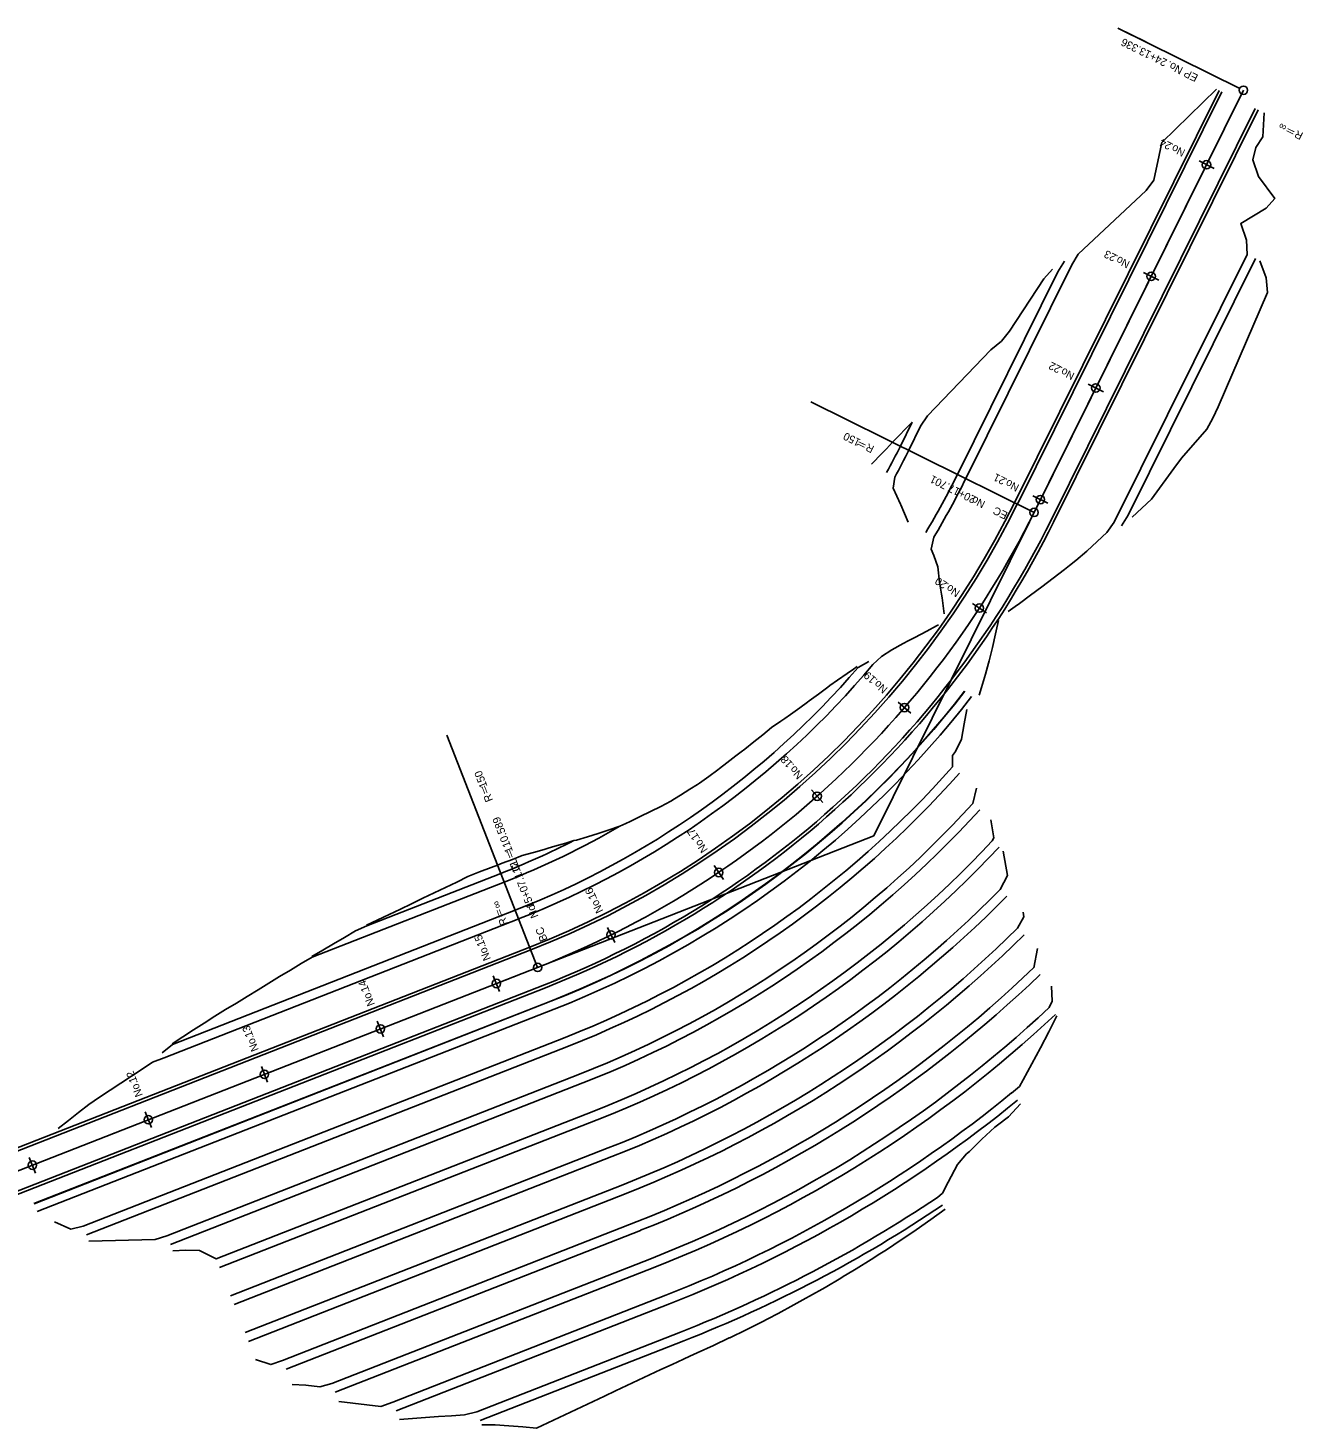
# Model space of a CAD drawing. Extents: x 46571 to 46965, y 10701 to 11034.
# Drawn here: x 46760.7 to 46965.4, y 10809 to 11033.7 of the extents above; entities that cross this region are included whole.
import ezdxf

# ---------------------------------------------------------------- set-up
doc = ezdxf.new("R2010")
doc.units = 0
for name, color, linetype in [('Default', 7, 'Continuous'), ('作業レイヤ1', 7, 'Continuous'), ('地形_土崖 コンクリート、堅固な石積等斜面（地理院地図Vector）', 7, 'Continuous'), ('建物_堅ろう建物_堅ろう建物（外周線）（地理院地図Vector）', 7, 'Continuous'), ('建物_普通建物_普通建物（外周線）（地理院地図Vector）', 7, 'Continuous'), ('河川_通常部（地理院地図Vector）', 7, 'Continuous'), ('現況_地形', 7, 'Continuous'), ('現況_地形_フロー矢印', 7, 'Continuous'), ('現況_地形_単点標高', 7, 'Continuous'), ('等高線等深線_等高線_主曲線通常部（地理院地図Vector）', 7, 'Continuous'), ('道路_通常部_通常部（地理院地図Vector）', 7, 'Continuous')]:
    doc.layers.add(name, color=color, linetype=linetype)

msp = doc.modelspace()

# ---------------------------------------------------------------- linework, layer by layer
at = {"layer": 'Default'}
for p, q in [((46955.22, 11024.01), (46935.66, 11033.7)), ((46935.66, 11033.7), (46940.14, 11031.48)), ((46896.47, 10904.04), (46955.82, 11023.71)), ((46922.21, 10955.95), (46955.82, 11023.71)), ((46955.82, 11023.71), (46955.82, 11023.71)), ((46949.89, 11011.76), (46949.89, 11011.76)), ((46941.01, 10993.84), (46941.01, 10993.84)), ((46932.12, 10975.92), (46932.12, 10975.92)), ((46922.21, 10955.95), (46886.38, 10973.72)), ((46923.23, 10958.01), (46923.23, 10958.01)), ((46922.21, 10955.95), (46922.21, 10955.95)), ((46913.43, 10940.59), (46913.43, 10940.59)), ((46901.41, 10924.62), (46901.41, 10924.62)), ((46842.51, 10882.92), (46827.93, 10920.17)), ((46887.38, 10910.39), (46887.38, 10910.39)), ((46679.76, 10819.21), (46896.47, 10904.04)), ((46871.58, 10898.15), (46871.58, 10898.15)), ((46854.29, 10888.13), (46854.29, 10888.13)), ((46720.93, 10835.33), (46842.51, 10882.92)), ((46842.51, 10882.92), (46842.51, 10882.92)), ((46835.89, 10880.33), (46835.89, 10880.33)), ((46817.26, 10873.04), (46817.26, 10873.04)), ((46798.64, 10865.75), (46798.64, 10865.75)), ((46780.01, 10858.46), (46780.01, 10858.46)), ((46761.39, 10851.17), (46761.39, 10851.17))]:
    msp.add_line(p, q, dxfattribs=at)
for centre in [(46955.82, 11023.71), (46949.89, 11011.76), (46941.01, 10993.84), (46932.12, 10975.92), (46923.23, 10958.01), (46922.21, 10955.95), (46913.43, 10940.59), (46901.41, 10924.62), (46887.38, 10910.39), (46871.58, 10898.15), (46854.29, 10888.13), (46842.51, 10882.92), (46835.89, 10880.33), (46817.26, 10873.04), (46798.64, 10865.75), (46780.01, 10858.46), (46761.39, 10851.17)]:
    msp.add_circle(centre, 0.675, dxfattribs=at)
msp.add_arc((46787.83, 11022.6), 150, 291.3768, 333.6189, dxfattribs=at)
msp.add_arc((46787.83, 11022.6), 150, 291.3768, 333.6189, dxfattribs=at)
at = {"layer": '作業レイヤ1'}
for p, q in [((46922.21, 10955.95), (46955.82, 11023.71)), ((46720.93, 10835.33), (46842.51, 10882.92))]:
    msp.add_line(p, q, dxfattribs=at)
msp.add_arc((46787.83, 11022.6), 150, 291.3768, 333.6189, dxfattribs=at)
at = {"layer": '地形_土崖 コンクリート、堅固な石積等斜面（地理院地図Vector）'}
for p, q in [((46919.53, 10957.28), (46952.35, 11023.46)), ((46924.9, 10954.61), (46957.72, 11020.79)), ((46719.83, 10838.12), (46841.42, 10885.71)), ((46722.02, 10832.53), (46843.6, 10880.12))]:
    msp.add_line(p, q, dxfattribs=at)
for radius in [147, 153]:
    msp.add_arc((46787.83, 11022.6), radius, 291.3768, 333.6189, dxfattribs=at)
at = {"layer": '建物_堅ろう建物_堅ろう建物（外周線）（地理院地図Vector）'}
msp.add_line((46761.64, 10845.04), (46844.62, 10877.52), dxfattribs=at)
msp.add_arc((46787.83, 11022.6), 155.8, 291.3768, 322.2738, dxfattribs=at)
at = {"layer": '建物_普通建物_普通建物（外周線）（地理院地図Vector）'}
for p, q in [((46919.08, 10957.5), (46951.9, 11023.68)), ((46925.35, 10954.39), (46958.17, 11020.57)), ((46719.65, 10838.59), (46841.23, 10886.18)), ((46722.2, 10832.07), (46843.78, 10879.66)), ((46762.16, 10843.71), (46845.14, 10876.19))]:
    msp.add_line(p, q, dxfattribs=at)
for radius, end in [(146.5, 333.6189), (153.5, 333.6189), (157.22, 322.2738)]:
    msp.add_arc((46787.83, 11022.6), radius, 291.3768, end, dxfattribs=at)
at = {"layer": '現況_地形'}
msp.add_line((46761.66, 10844.99), (46844.64, 10877.47), dxfattribs=at)
msp.add_arc((46787.83, 11022.6), 155.85, 291.3768, 322.2738, dxfattribs=at)
at = {"layer": '現況_地形_フロー矢印'}
msp.add_line((46900.75, 10966.59), (46902.66, 10970.45), dxfattribs=at)
for points in [[(46911.26, 10961.38), (46928.27, 10995.69), (46929.31, 10997.41), (46940.19, 11007.64), (46941.42, 11009.27), (46942.28, 11013.3), (46942.72, 11015.32), (46951.52, 11023.87)], [(46918.04, 10940.04), (46919.19, 10940.86), (46919.85, 10941.34), (46921.65, 10942.67), (46923.46, 10944.02), (46925.27, 10945.4), (46927.08, 10946.81), (46927.89, 10947.45), (46928.89, 10948.24), (46930.66, 10949.73), (46932.33, 10951.26), (46933.91, 10952.71), (46935.08, 10954.36), (46956.41, 10997.37), (46956.34, 10999.63), (46955.38, 11002.34), (46959.47, 11004.78), (46960.85, 11006.32), (46958.23, 11009.86), (46957.32, 11012.54), (46957.81, 11014.53), (46958.92, 11016.21), (46959.17, 11020.07)], [(46909.91, 10962.05), (46926.04, 10994.57), (46927.07, 10996.29)], [(46936.25, 10953.78), (46937.31, 10955.49), (46957.75, 10996.7)], [(46937.94, 10955.18), (46939.52, 10956.63), (46941.07, 10958.09), (46944.66, 10963.01), (46945.87, 10964.64), (46949.96, 10969.31), (46950.92, 10971.07), (46951.77, 10972.87), (46959.7, 10991.27), (46959.47, 10993.61), (46958.48, 10996.34)], [(46902.09, 10965.93), (46904, 10969.78), (46905.09, 10971.47), (46915.28, 10982.04), (46916.97, 10983.44), (46918.26, 10985.03), (46923.76, 10993.46), (46925.16, 10995)], [(46896.09, 10963.67), (46896.63, 10964.22), (46897.29, 10964.9), (46898.49, 10966.14), (46899.5, 10967.22), (46902.63, 10970.46)], [(46902, 10954.4), (46900.8, 10957.15), (46900.75, 10957.27), (46899.58, 10959.83), (46899.86, 10961.63)], [(46907.76, 10939.65), (46907.43, 10942.22), (46907.34, 10942.81), (46907.02, 10944.77), (46906.75, 10947.19), (46906.11, 10949.01), (46905.68, 10950.06), (46906.11, 10951.95)]]:
    msp.add_lwpolyline(points, dxfattribs=at)
for radius, start in [(126.04, 331.4411), (127.54, 331.4411), (136.27, 329.1493), (137.77, 329.1493)]:
    msp.add_arc((46787.83, 11022.6), radius, start, 333.6189, dxfattribs=at)
at = {"layer": '現況_地形_単点標高'}
for p, q in [((46893.96, 10931.06), (46895.7, 10932.03)), ((46912.38, 10909.23), (46912.97, 10911.71)), ((46922.16, 10882.87), (46922.75, 10885.95)), ((46770.06, 10839.99), (46847.46, 10870.28)), ((46783.55, 10838.45), (46849.77, 10864.37)), ((46791.45, 10834.72), (46852.09, 10858.45)), ((46793.22, 10830.2), (46853.85, 10853.94)), ((46793.77, 10828.81), (46854.4, 10852.54)), ((46795.54, 10824.29), (46856.17, 10848.02)), ((46796.08, 10822.89), (46856.71, 10846.63)), ((46802.12, 10818.44), (46859.03, 10840.71)), ((46810.02, 10814.71), (46861.34, 10834.8)), ((46819.79, 10811.72), (46863.66, 10828.89)), ((46833.28, 10810.18), (46865.97, 10822.97))]:
    msp.add_line(p, q, dxfattribs=at)
for points in [[(46896.32, 10931.51), (46897.7, 10932.82), (46899.38, 10933.9), (46901.19, 10934.9), (46901.99, 10935.32), (46903.07, 10935.88), (46904.97, 10936.87), (46906.55, 10937.72), (46906.87, 10937.9)], [(46913.38, 10926.61), (46913.76, 10927.84), (46914.39, 10929.98), (46914.89, 10931.76), (46914.99, 10932.12), (46915.53, 10934.28), (46916.02, 10936.44), (46916.13, 10936.94), (46916.48, 10938.6)], [(46855.73, 10905.57), (46856.66, 10906.03), (46857.36, 10906.36), (46858.99, 10907.14), (46860.63, 10907.94), (46862.26, 10908.76), (46863.87, 10909.61), (46864.47, 10909.98), (46865.42, 10910.56), (46866.96, 10911.53), (46868.18, 10912.3), (46868.5, 10912.51), (46869.98, 10913.57), (46871.45, 10914.65), (46871.73, 10914.86), (46872.9, 10915.74), (46874.35, 10916.85), (46875.21, 10917.51), (46875.79, 10917.97), (46877.22, 10919.1), (46878.65, 10920.24), (46880.06, 10921.4), (46881.57, 10922.46), (46882.18, 10922.88), (46883.09, 10923.51), (46884.6, 10924.59), (46885.83, 10925.47), (46886.11, 10925.68), (46887.62, 10926.78), (46889.12, 10927.9), (46889.44, 10928.14), (46890.63, 10929.03), (46892.22, 10930.1), (46893.2, 10930.77), (46893.8, 10931.19)], [(46909.13, 10915.11), (46909.09, 10916.92), (46909.59, 10917.57), (46910.55, 10919.56), (46911.01, 10922.01), (46911.41, 10924.33)], [(46915.5, 10903.24), (46915.73, 10903.71), (46915.25, 10906.62)], [(46848.34, 10903.26), (46848.76, 10903.36), (46850.51, 10903.85), (46852.24, 10904.43), (46853.97, 10905.02), (46855.7, 10905.61)], [(46815.05, 10889.67), (46816.85, 10890.54), (46818.66, 10891.41), (46820.47, 10892.27), (46822.28, 10893.14), (46824.09, 10894.01), (46825.89, 10894.88), (46827.7, 10895.75), (46829.51, 10896.62), (46831.31, 10897.51), (46833.17, 10898.24), (46835.04, 10898.94), (46836.08, 10899.34), (46836.81, 10899.62), (46838.46, 10900.25), (46840.04, 10900.86), (46841.83, 10901.36), (46843.56, 10901.85), (46844.18, 10902.03), (46845.28, 10902.35), (46847.01, 10902.87), (46848.33, 10903.28)], [(46916.79, 10895.42), (46917.92, 10897.69), (46917.27, 10901.58)], [(46806.27, 10884.67), (46808.01, 10885.69), (46809.76, 10886.71), (46811.51, 10887.73), (46813.26, 10888.76), (46815.08, 10889.58), (46836.6, 10898)], [(46783.83, 10870.65), (46785.54, 10871.77), (46787.25, 10872.89), (46788.97, 10873.99), (46790.68, 10875.09), (46792.42, 10876.15), (46794.15, 10877.2), (46795.89, 10878.26), (46797.62, 10879.32), (46799.36, 10880.37), (46801.09, 10881.43), (46802.82, 10882.49), (46804.55, 10883.55), (46806.32, 10884.54), (46837.15, 10896.61)], [(46765.54, 10857.04), (46767.18, 10858.32), (46768.82, 10859.61), (46770.47, 10860.9), (46772.15, 10862.09), (46773.86, 10863.21), (46775.57, 10864.32), (46777.28, 10865.44), (46778.99, 10866.56), (46780.7, 10867.69), (46782.56, 10868.42), (46839.47, 10890.69)], [(46782.25, 10869.22), (46783.87, 10870.54), (46838.92, 10892.09)], [(46919.55, 10889.19), (46920.58, 10891.02), (46920.48, 10891.78)], [(46924.62, 10876.46), (46925.13, 10877.49), (46925, 10879.92)], [(46918.6, 10862.75), (46919.85, 10863.82), (46920.44, 10864.85), (46921.86, 10867.41), (46923.23, 10869.99), (46924.56, 10872.57), (46925.84, 10875.16)], [(46764.96, 10842.05), (46767.56, 10840.88), (46769.52, 10841.38), (46846.91, 10871.68)], [(46770.47, 10838.95), (46774.72, 10839.07), (46776.84, 10839.13), (46778.97, 10839.18), (46781.09, 10839.25), (46783, 10839.84), (46849.22, 10865.76)], [(46906.68, 10845.99), (46907.52, 10846.7), (46908.44, 10848.44), (46909.89, 10851.27), (46911.38, 10852.98), (46911.82, 10853.39), (46913.84, 10855.36), (46915.89, 10857.26), (46916.32, 10857.58), (46918.11, 10858.95), (46920.04, 10861)], [(46783.96, 10837.4), (46786.05, 10837.54), (46788.22, 10837.5), (46790.91, 10836.12), (46851.54, 10859.85)], [(46833.55, 10809.47), (46835.7, 10809.48), (46837.91, 10809.31), (46840.12, 10809.15), (46842.34, 10808.98), (46844.16, 10809.81), (46845.97, 10810.67), (46847.78, 10811.53), (46849.59, 10812.39), (46851.41, 10813.24), (46853.22, 10814.1), (46855.03, 10814.95), (46856.85, 10815.81), (46858.66, 10816.66), (46860.48, 10817.51), (46862.29, 10818.35), (46864.11, 10819.2), (46865.92, 10820.05), (46866.93, 10820.52), (46868.11, 10821.04), (46870.74, 10822.24), (46873.26, 10823.43), (46873.36, 10823.48), (46875.96, 10824.74), (46878.54, 10826.04), (46879.47, 10826.52), (46881.1, 10827.38), (46883.64, 10828.74), (46885.59, 10829.81), (46886.17, 10830.14), (46888.67, 10831.56), (46891.16, 10833.02), (46891.58, 10833.28), (46893.12, 10834.2), (46893.62, 10834.51), (46896.07, 10836.04), (46897.46, 10836.93), (46898.49, 10837.59), (46900.89, 10839.17), (46903.22, 10840.76), (46903.26, 10840.79), (46905.62, 10842.44), (46907.95, 10844.11)], [(46797.22, 10819.99), (46799.69, 10819.17), (46801.57, 10819.84), (46858.48, 10842.11)], [(46803.09, 10815.98), (46805.28, 10815.85), (46807.53, 10815.59), (46809.48, 10816.11), (46860.8, 10836.2)], [(46810.6, 10813.24), (46812.85, 10812.97), (46815.1, 10812.71), (46817.36, 10812.44), (46819.24, 10813.11), (46863.11, 10830.28)], [(46820.32, 10810.36), (46822.41, 10810.51), (46824.49, 10810.66), (46826.58, 10810.81), (46828.67, 10810.96), (46830.76, 10811.11), (46832.73, 10811.57), (46865.43, 10824.37)]]:
    msp.add_lwpolyline(points, dxfattribs=at)
for radius, end in [(140.15, 319.218), (141.65, 319.982), (162.07, 318.4541), (163.57, 318.4541), (168.42, 317.6902), (169.92, 317.6902), (135.3, 300.1195), (133.8, 296.8866), (174.77, 316.9262), (176.27, 316.9262), (181.12, 315.3983), (182.62, 315.3983), (187.47, 314.6344), (188.97, 314.6344), (193.82, 313.8704), (195.32, 313.8704), (200.17, 313.1065), (201.67, 313.1065), (206.52, 309.2868), (208.02, 309.2868), (212.87, 303.9392), (214.37, 303.9392)]:
    msp.add_arc((46787.83, 11022.6), radius, 291.3768, end, dxfattribs=at)
at = {"layer": '等高線等深線_等高線_主曲線通常部（地理院地図Vector）'}
for p, q in [((46922.21, 10955.95), (46955.82, 11023.71)), ((46720.93, 10835.33), (46842.51, 10882.92))]:
    msp.add_line(p, q, dxfattribs=at)
msp.add_arc((46787.83, 11022.6), 150, 291.3768, 333.6189, dxfattribs=at)
at = {"layer": '道路_通常部_通常部（地理院地図Vector）'}
for p, q in [((46948.69, 11012.36), (46951.1, 11011.16)), ((46939.8, 10994.44), (46942.22, 10993.24)), ((46930.91, 10976.52), (46933.33, 10975.32)), ((46922.02, 10958.61), (46924.44, 10957.41)), ((46912.3, 10941.33), (46914.56, 10939.85)), ((46900.39, 10925.5), (46902.44, 10923.74)), ((46886.49, 10911.4), (46888.28, 10909.38)), ((46870.83, 10899.27), (46872.33, 10897.03)), ((46853.7, 10889.34), (46854.89, 10886.92)), ((46835.39, 10881.58), (46836.38, 10879.07)), ((46816.77, 10874.29), (46817.75, 10871.78)), ((46798.15, 10867), (46799.13, 10864.49)), ((46779.52, 10859.71), (46780.51, 10857.2)), ((46760.9, 10852.42), (46761.88, 10849.91))]:
    msp.add_line(p, q, dxfattribs=at)

# ---------------------------------------------------------------- texts
at = {"layer": 'Default'}
for s, rotation, p in [('24+13.336', 153.6189, (46943.69, 11028.58)), ('EP No.', 153.6189, (46948.65, 11026.12)), ('R＝∞', 153.6189, (46965.51, 11016.81)), ('150', 153.6189, (46894.48, 10967.61)), ('R＝', 153.6189, (46896.66, 10966.53)), ('20+17.701', 153.6189, (46913.01, 10958.42)), ('EC\u3000No.', 153.6189, (46918.1, 10955.89)), ('150', 111.3768, (46834.47, 10912.02)), ('R＝', 111.3768, (46835.36, 10909.75)), ('110.589', 111.3768, (46838.56, 10901.59)), ('CL＝', 111.3768, (46839.74, 10898.57)), ('15+07.112', 111.3768, (46842.05, 10892.65)), ('R＝∞', 111.3768, (46837.75, 10889.92)), ('BC\u3000No.', 111.3768, (46844.13, 10887.36))]:
    msp.add_text(s, height=1.25, rotation=rotation, dxfattribs=at).set_placement(p)
at = {"layer": '河川_通常部（地理院地図Vector）'}
for s, rotation, p in [('24', 153.6189, (46944.41, 11015.18)), ('No.', 153.6189, (46946.59, 11014.1)), ('23', 153.6189, (46935.52, 10997.26)), ('No.', 153.6189, (46937.7, 10996.18)), ('22', 153.6189, (46926.63, 10979.34)), ('No.', 153.6189, (46928.82, 10978.26)), ('21', 153.6189, (46917.75, 10961.43)), ('No.', 153.6189, (46919.93, 10960.34)), ('20', 146.8575, (46908.38, 10944.63)), ('No.', 146.8575, (46910.42, 10943.3)), ('19', 139.218, (46896.95, 10929.3)), ('No.', 139.218, (46898.79, 10927.71)), ('18', 131.5786, (46883.58, 10915.62)), ('No.', 131.5786, (46885.19, 10913.8)), ('17', 123.9392, (46868.51, 10903.84)), ('No.', 123.9392, (46869.87, 10901.82)), ('16', 116.2997, (46852, 10894.17)), ('No.', 116.2997, (46853.08, 10891.99)), ('15', 111.3768, (46834.12, 10886.55)), ('No.', 111.3768, (46835.01, 10884.28)), ('14', 111.3768, (46815.5, 10879.26)), ('No.', 111.3768, (46816.39, 10876.99)), ('13', 111.3768, (46796.87, 10871.97)), ('No.', 111.3768, (46797.76, 10869.7)), ('12', 111.3768, (46778.25, 10864.68)), ('No.', 111.3768, (46779.14, 10862.41))]:
    msp.add_text(s, height=1.25, rotation=rotation, dxfattribs=at).set_placement(p)

doc.saveas('drawing.dxf')
